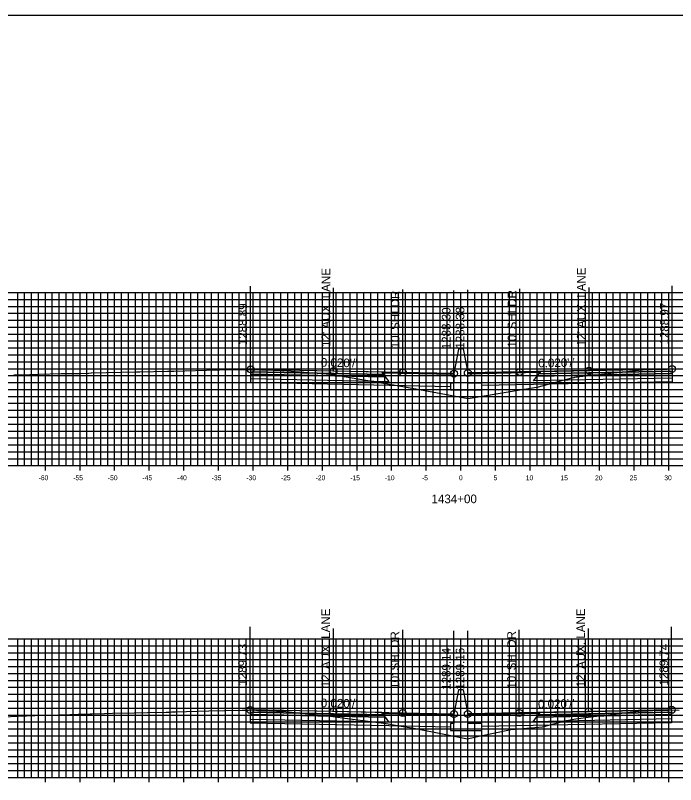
# Model space of a CAD drawing. Extents: x 674939 to 678919, y 750652 to 765176.
# Drawn here: x 678674.2 to 678769.5, y 758391.5 to 758502.6 of the extents above; entities that cross this region are included whole.
import ezdxf

# ---------------------------------------------------------------- set-up
doc = ezdxf.new("R2010")
doc.units = 0
for name, color, linetype in [('Level 10', 7, 'Continuous'), ('Level 17', 7, 'Continuous'), ('Level 18', 7, 'Continuous'), ('Level 19', 7, 'Continuous'), ('Level 20', 7, 'Continuous'), ('Level 22', 7, 'Continuous'), ('Level 23', 7, 'Continuous'), ('Level 4', 7, 'Continuous'), ('Level 8', 7, 'Continuous'), ('Level 9', 7, 'Continuous')]:
    doc.layers.add(name, color=color, linetype=linetype)

msp = doc.modelspace()

# ---------------------------------------------------------------- linework, layer by layer
at = {"layer": 'Level 10'}
for points in [[(678673.98, 758450.67), (678676.27, 758450.71), (678676.43, 758450.71), (678677.58, 758450.76), (678680.82, 758450.84), (678681.07, 758450.84), (678683.36, 758450.86), (678683.42, 758450.86), (678684.76, 758450.9), (678684.77, 758450.91), (678684.78, 758450.91), (678685.16, 758450.93), (678685.18, 758450.93), (678691.68, 758451.09), (678691.98, 758451.1), (678692.17, 758451.1), (678696.18, 758451.17), (678696.94, 758451.2), (678697.1, 758451.2), (678703.4, 758451.37), (678703.66, 758451.38), (678707.67, 758451.44), (678707.78, 758451.44), (678707.79, 758451.44), (678708.15, 758451.44), (678708.15, 758451.44), (678708.37, 758451.44), (678708.4, 758451.43), (678709.74, 758451.37), (678709.78, 758451.37), (678709.81, 758451.37), (678711.53, 758451.33), (678711.55, 758451.33), (678711.62, 758451.33), (678712.77, 758451.28), (678712.78, 758451.29), (678712.78, 758451.29), (678715.86, 758451.07), (678719.7, 758450.76), (678726.77, 758449.57), (678728.53, 758449.26), (678732.54, 758448.55), (678739.6, 758447.23), (678745.95, 758448.32), (678749.71, 758448.94), (678754.56, 758450.22), (678754.79, 758450.29), (678754.86, 758450.3), (678754.98, 758450.34), (678755.22, 758450.36), (678755.34, 758450.38), (678755.71, 758450.42), (678764.65, 758451.38), (678764.66, 758451.37), (678764.7, 758451.36), (678764.76, 758451.36), (678765.97, 758451.42), (678766.21, 758451.43), (678767.77, 758451.47), (678767.99, 758451.48), (678768.33, 758451.47), (678768.96, 758451.51), (678769.03, 758451.52), (678769.05, 758451.52), (678769.28, 758451.53), (678770.34, 758451.52)], [(678671.84, 758401.22), (678674.26, 758401.4), (678674.61, 758401.41), (678677.03, 758401.49), (678678.68, 758401.54), (678682.1, 758401.63), (678682.97, 758401.65), (678683.25, 758401.66), (678684.25, 758401.66), (678684.53, 758401.68), (678684.98, 758401.72), (678685.1, 758401.73), (678685.22, 758401.74), (678687.08, 758401.78), (678688.23, 758401.81), (678691.36, 758401.89), (678693.26, 758401.93), (678695.97, 758401.97), (678696.08, 758401.97), (678696.51, 758401.97), (678696.74, 758401.99), (678697.31, 758402.03), (678702.15, 758402.15), (678704.4, 758402.21), (678706.96, 758402.25), (678707.87, 758402.26), (678708.12, 758402.28), (678708.15, 758402.28), (678708.22, 758402.28), (678708.94, 758402.23), (678709.22, 758402.21), (678709.4, 758402.2), (678709.45, 758402.21), (678709.63, 758402.2), (678711.91, 758402.13), (678712.42, 758402.11), (678712.71, 758402.11), (678712.78, 758402.11), (678712.83, 758402.13), (678717.4, 758401.63), (678719.03, 758401.45), (678719.69, 758401.38), (678720.39, 758401.3), (678721.78, 758401.11), (678727.72, 758400.33), (678729.89, 758399.95), (678731.97, 758399.59), (678736.1, 758398.8), (678739.49, 758398.12), (678740.5, 758398.35), (678745.76, 758399.45), (678749.2, 758399.76), (678750.31, 758399.87), (678753.77, 758400.75), (678755.1, 758400.99), (678756.89, 758401.26), (678764.59, 758402.17), (678764.68, 758402.15), (678764.99, 758402.15), (678765.36, 758402.18), (678765.68, 758402.19), (678766.25, 758402.22), (678766.88, 758402.25), (678767.07, 758402.24), (678767.28, 758402.22), (678767.85, 758402.23), (678768.38, 758402.24), (678768.59, 758402.28), (678768.78, 758402.3), (678768.87, 758402.3), (678768.96, 758402.3), (678770.03, 758402.27)]]:
    msp.add_lwpolyline(points, dxfattribs=at)
at = {"layer": 'Level 17'}
for points in [[(678738.2, 758454.35), (678737.53, 758450.85)], [(678738.86, 758454.43), (678738.86, 758454.43), (678738.2, 758454.43), (678738.2, 758454.35)], [(678738.86, 758454.43), (678739.53, 758450.93)], [(678737.53, 758450.85), (678737.53, 758449.48), (678737.03, 758449.48), (678737.03, 758448.48), (678741.53, 758448.48), (678741.53, 758449.48), (678739.53, 758449.48), (678739.53, 758450.93)], [(678738.2, 758405.19), (678737.53, 758401.69)], [(678738.86, 758405.21), (678738.86, 758405.21), (678738.2, 758405.21), (678738.2, 758405.19)], [(678738.86, 758405.21), (678739.53, 758401.71)], [(678737.53, 758401.69), (678737.53, 758400.32), (678737.03, 758400.32), (678737.03, 758399.32), (678741.53, 758399.32), (678741.53, 758400.32), (678739.53, 758400.32), (678739.53, 758401.71)]]:
    msp.add_lwpolyline(points, dxfattribs=at)
at = {"layer": 'Level 18'}
for points in [[(678737.53, 758450.85), (678730.15, 758451), (678720.15, 758451.2), (678708.15, 758451.44)], [(678769.03, 758451.52), (678757.03, 758451.28), (678747.03, 758451.08), (678739.53, 758450.93)], [(678737.53, 758401.69), (678730.12, 758401.84), (678720.12, 758402.04), (678708.12, 758402.28)], [(678768.96, 758402.3), (678756.96, 758402.06), (678746.96, 758401.86), (678739.53, 758401.71)]]:
    msp.add_lwpolyline(points, dxfattribs=at)
for points in [[(678708.15, 758451.44), (678708.15, 758451.11), (678727.4, 758450.72), (678727.15, 758451.06)], [(678769.03, 758451.52), (678769.03, 758451.19), (678749.78, 758450.8), (678750.03, 758451.14)], [(678727.15, 758451.06), (678737.53, 758450.85), (678737.54, 758450.69), (678727.27, 758450.9)], [(678749.91, 758450.98), (678739.53, 758450.77), (678739.53, 758450.93), (678750.03, 758451.14)], [(678708.12, 758402.28), (678708.12, 758401.95), (678727.37, 758401.57), (678727.12, 758401.9)], [(678727.12, 758401.9), (678737.53, 758401.69), (678737.54, 758401.53), (678727.24, 758401.74)], [(678749.84, 758401.76), (678739.53, 758401.55), (678739.53, 758401.71), (678749.96, 758401.92)], [(678768.96, 758402.3), (678768.96, 758401.97), (678749.71, 758401.58), (678749.96, 758401.92)]]:
    msp.add_lwpolyline(points, close=True, dxfattribs=at)
at = {"layer": 'Level 19'}
for points in [[(678708.15, 758451.11), (678708.15, 758450.78), (678727.65, 758450.39), (678727.4, 758450.72)], [(678708.15, 758450.78), (678708.15, 758450.12), (678728.15, 758449.72), (678727.65, 758450.39)], [(678769.03, 758450.86), (678769.03, 758450.2), (678749.03, 758449.8), (678749.53, 758450.47)], [(678769.03, 758451.19), (678769.03, 758450.86), (678749.53, 758450.47), (678749.78, 758450.8)], [(678708.12, 758401.95), (678708.12, 758401.62), (678727.62, 758401.23), (678727.37, 758401.57)], [(678708.12, 758401.62), (678708.12, 758400.96), (678728.12, 758400.56), (678727.62, 758401.23)], [(678768.96, 758401.64), (678768.96, 758400.98), (678748.96, 758400.58), (678749.46, 758401.25)], [(678768.96, 758401.97), (678768.96, 758401.64), (678749.46, 758401.25), (678749.71, 758401.58)]]:
    msp.add_lwpolyline(points, close=True, dxfattribs=at)
for points in [[(678708.15, 758450.12), (678708.15, 758449.58), (678728.15, 758449.18), (678737.03, 758449)], [(678769.03, 758450.2), (678769.03, 758449.66), (678749.03, 758449.26), (678741.53, 758449.11)], [(678708.12, 758400.96), (678708.12, 758400.42), (678728.12, 758400.02), (678737.03, 758399.84)], [(678768.96, 758400.98), (678768.96, 758400.44), (678748.96, 758400.04), (678741.53, 758399.89)]]:
    msp.add_lwpolyline(points, dxfattribs=at)
at = {"layer": 'Level 20'}
for p, q in [((678638.53, 758462.55), (678838.53, 758462.55)), ((678674.53, 758437.55), (678674.53, 758462.55)), ((678675.53, 758437.55), (678675.53, 758462.55)), ((678676.53, 758437.55), (678676.53, 758462.55)), ((678677.53, 758437.55), (678677.53, 758462.55)), ((678678.53, 758437.55), (678678.53, 758462.55)), ((678679.53, 758437.55), (678679.53, 758462.55)), ((678680.53, 758437.55), (678680.53, 758462.55)), ((678681.53, 758437.55), (678681.53, 758462.55)), ((678682.53, 758437.55), (678682.53, 758462.55)), ((678683.53, 758437.55), (678683.53, 758462.55)), ((678684.53, 758437.55), (678684.53, 758462.55)), ((678685.53, 758437.55), (678685.53, 758462.55)), ((678686.53, 758437.55), (678686.53, 758462.55)), ((678687.53, 758437.55), (678687.53, 758462.55)), ((678688.53, 758437.55), (678688.53, 758462.55)), ((678689.53, 758437.55), (678689.53, 758462.55)), ((678690.53, 758437.55), (678690.53, 758462.55)), ((678691.53, 758437.55), (678691.53, 758462.55)), ((678692.53, 758437.55), (678692.53, 758462.55)), ((678693.53, 758437.55), (678693.53, 758462.55)), ((678694.53, 758437.55), (678694.53, 758462.55)), ((678695.53, 758437.55), (678695.53, 758462.55)), ((678696.53, 758437.55), (678696.53, 758462.55)), ((678697.53, 758437.55), (678697.53, 758462.55)), ((678698.53, 758437.55), (678698.53, 758462.55)), ((678699.53, 758437.55), (678699.53, 758462.55)), ((678700.53, 758437.55), (678700.53, 758462.55)), ((678701.53, 758437.55), (678701.53, 758462.55)), ((678702.53, 758437.55), (678702.53, 758462.55)), ((678703.53, 758437.55), (678703.53, 758462.55)), ((678704.53, 758437.55), (678704.53, 758462.55)), ((678705.53, 758437.55), (678705.53, 758462.55)), ((678706.53, 758437.55), (678706.53, 758462.55)), ((678707.53, 758437.55), (678707.53, 758462.55)), ((678708.53, 758437.55), (678708.53, 758462.55)), ((678709.53, 758437.55), (678709.53, 758462.55)), ((678710.53, 758437.55), (678710.53, 758462.55)), ((678711.53, 758437.55), (678711.53, 758462.55)), ((678712.53, 758437.55), (678712.53, 758462.55)), ((678713.53, 758437.55), (678713.53, 758462.55)), ((678714.53, 758437.55), (678714.53, 758462.55)), ((678715.53, 758437.55), (678715.53, 758462.55)), ((678716.53, 758437.55), (678716.53, 758462.55)), ((678717.53, 758437.55), (678717.53, 758462.55)), ((678718.53, 758437.55), (678718.53, 758462.55)), ((678719.53, 758437.55), (678719.53, 758462.55)), ((678720.53, 758437.55), (678720.53, 758462.55)), ((678721.53, 758437.55), (678721.53, 758462.55)), ((678722.53, 758437.55), (678722.53, 758462.55)), ((678723.53, 758437.55), (678723.53, 758462.55)), ((678724.53, 758437.55), (678724.53, 758462.55)), ((678725.53, 758437.55), (678725.53, 758462.55)), ((678726.53, 758437.55), (678726.53, 758462.55)), ((678727.53, 758437.55), (678727.53, 758462.55)), ((678728.53, 758437.55), (678728.53, 758462.55)), ((678729.53, 758437.55), (678729.53, 758462.55)), ((678730.53, 758437.55), (678730.53, 758462.55)), ((678731.53, 758437.55), (678731.53, 758462.55)), ((678732.53, 758437.55), (678732.53, 758462.55)), ((678733.53, 758437.55), (678733.53, 758462.55)), ((678734.53, 758437.55), (678734.53, 758462.55)), ((678735.53, 758437.55), (678735.53, 758462.55)), ((678736.53, 758437.55), (678736.53, 758462.55)), ((678737.53, 758437.55), (678737.53, 758462.55)), ((678738.53, 758437.55), (678738.53, 758462.55)), ((678739.53, 758437.55), (678739.53, 758462.55)), ((678740.53, 758437.55), (678740.53, 758462.55)), ((678741.53, 758437.55), (678741.53, 758462.55)), ((678742.53, 758437.55), (678742.53, 758462.55)), ((678743.53, 758437.55), (678743.53, 758462.55)), ((678744.53, 758437.55), (678744.53, 758462.55)), ((678745.53, 758437.55), (678745.53, 758462.55)), ((678746.53, 758437.55), (678746.53, 758462.55)), ((678747.53, 758437.55), (678747.53, 758462.55)), ((678748.53, 758437.55), (678748.53, 758462.55)), ((678749.53, 758437.55), (678749.53, 758462.55)), ((678750.53, 758437.55), (678750.53, 758462.55)), ((678751.53, 758437.55), (678751.53, 758462.55)), ((678752.53, 758437.55), (678752.53, 758462.55)), ((678753.53, 758437.55), (678753.53, 758462.55)), ((678754.53, 758437.55), (678754.53, 758462.55)), ((678755.53, 758437.55), (678755.53, 758462.55)), ((678756.53, 758437.55), (678756.53, 758462.55)), ((678757.53, 758437.55), (678757.53, 758462.55)), ((678758.53, 758437.55), (678758.53, 758462.55)), ((678759.53, 758437.55), (678759.53, 758462.55)), ((678760.53, 758437.55), (678760.53, 758462.55)), ((678761.53, 758437.55), (678761.53, 758462.55)), ((678762.53, 758437.55), (678762.53, 758462.55)), ((678763.53, 758437.55), (678763.53, 758462.55)), ((678764.53, 758437.55), (678764.53, 758462.55)), ((678765.53, 758437.55), (678765.53, 758462.55)), ((678766.53, 758437.55), (678766.53, 758462.55)), ((678767.53, 758437.55), (678767.53, 758462.55)), ((678768.53, 758437.55), (678768.53, 758462.55)), ((678638.53, 758461.55), (678838.53, 758461.55)), ((678638.53, 758460.55), (678838.53, 758460.55)), ((678638.53, 758459.55), (678838.53, 758459.55)), ((678638.53, 758458.55), (678838.53, 758458.55)), ((678638.53, 758457.55), (678838.53, 758457.55)), ((678638.53, 758456.55), (678838.53, 758456.55)), ((678638.53, 758455.55), (678838.53, 758455.55)), ((678638.53, 758454.55), (678838.53, 758454.55)), ((678638.53, 758453.55), (678838.53, 758453.55)), ((678638.53, 758452.55), (678838.53, 758452.55)), ((678638.53, 758451.55), (678838.53, 758451.55)), ((678638.53, 758450.55), (678838.53, 758450.55)), ((678638.53, 758449.55), (678838.53, 758449.55)), ((678638.53, 758448.55), (678838.53, 758448.55)), ((678638.53, 758447.55), (678838.53, 758447.55)), ((678638.53, 758446.55), (678838.53, 758446.55)), ((678638.53, 758445.55), (678838.53, 758445.55)), ((678638.53, 758444.55), (678838.53, 758444.55)), ((678638.53, 758443.55), (678838.53, 758443.55)), ((678638.53, 758442.55), (678838.53, 758442.55)), ((678638.53, 758441.55), (678838.53, 758441.55)), ((678638.53, 758440.55), (678838.53, 758440.55)), ((678638.53, 758439.55), (678838.53, 758439.55)), ((678638.53, 758438.55), (678838.53, 758438.55)), ((678638.53, 758437.55), (678838.53, 758437.55)), ((678638.53, 758412.55), (678838.53, 758412.55)), ((678638.53, 758411.55), (678838.53, 758411.55)), ((678674.53, 758392.55), (678674.53, 758412.55)), ((678675.53, 758392.55), (678675.53, 758412.55)), ((678676.53, 758392.55), (678676.53, 758412.55)), ((678677.53, 758392.55), (678677.53, 758412.55)), ((678678.53, 758392.55), (678678.53, 758412.55)), ((678679.53, 758392.55), (678679.53, 758412.55)), ((678680.53, 758392.55), (678680.53, 758412.55)), ((678681.53, 758392.55), (678681.53, 758412.55)), ((678682.53, 758392.55), (678682.53, 758412.55)), ((678683.53, 758392.55), (678683.53, 758412.55)), ((678684.53, 758392.55), (678684.53, 758412.55)), ((678685.53, 758392.55), (678685.53, 758412.55)), ((678686.53, 758392.55), (678686.53, 758412.55)), ((678687.53, 758392.55), (678687.53, 758412.55)), ((678688.53, 758392.55), (678688.53, 758412.55)), ((678689.53, 758392.55), (678689.53, 758412.55)), ((678690.53, 758392.55), (678690.53, 758412.55)), ((678691.53, 758392.55), (678691.53, 758412.55)), ((678692.53, 758392.55), (678692.53, 758412.55)), ((678693.53, 758392.55), (678693.53, 758412.55)), ((678694.53, 758392.55), (678694.53, 758412.55)), ((678695.53, 758392.55), (678695.53, 758412.55)), ((678696.53, 758392.55), (678696.53, 758412.55)), ((678697.53, 758392.55), (678697.53, 758412.55)), ((678698.53, 758392.55), (678698.53, 758412.55)), ((678699.53, 758392.55), (678699.53, 758412.55)), ((678700.53, 758392.55), (678700.53, 758412.55)), ((678701.53, 758392.55), (678701.53, 758412.55)), ((678702.53, 758392.55), (678702.53, 758412.55)), ((678703.53, 758392.55), (678703.53, 758412.55)), ((678704.53, 758392.55), (678704.53, 758412.55)), ((678705.53, 758392.55), (678705.53, 758412.55)), ((678706.53, 758392.55), (678706.53, 758412.55)), ((678707.53, 758392.55), (678707.53, 758412.55)), ((678708.53, 758392.55), (678708.53, 758412.55)), ((678709.53, 758392.55), (678709.53, 758412.55)), ((678710.53, 758392.55), (678710.53, 758412.55)), ((678711.53, 758392.55), (678711.53, 758412.55)), ((678712.53, 758392.55), (678712.53, 758412.55)), ((678713.53, 758392.55), (678713.53, 758412.55)), ((678714.53, 758392.55), (678714.53, 758412.55)), ((678715.53, 758392.55), (678715.53, 758412.55)), ((678716.53, 758392.55), (678716.53, 758412.55)), ((678717.53, 758392.55), (678717.53, 758412.55)), ((678718.53, 758392.55), (678718.53, 758412.55)), ((678719.53, 758392.55), (678719.53, 758412.55)), ((678720.53, 758392.55), (678720.53, 758412.55)), ((678721.53, 758392.55), (678721.53, 758412.55)), ((678722.53, 758392.55), (678722.53, 758412.55)), ((678723.53, 758392.55), (678723.53, 758412.55)), ((678724.53, 758392.55), (678724.53, 758412.55)), ((678725.53, 758392.55), (678725.53, 758412.55)), ((678726.53, 758392.55), (678726.53, 758412.55)), ((678727.53, 758392.55), (678727.53, 758412.55)), ((678728.53, 758392.55), (678728.53, 758412.55)), ((678729.53, 758392.55), (678729.53, 758412.55)), ((678730.53, 758392.55), (678730.53, 758412.55)), ((678731.53, 758392.55), (678731.53, 758412.55)), ((678732.53, 758392.55), (678732.53, 758412.55)), ((678733.53, 758392.55), (678733.53, 758412.55)), ((678734.53, 758392.55), (678734.53, 758412.55)), ((678735.53, 758392.55), (678735.53, 758412.55)), ((678736.53, 758392.55), (678736.53, 758412.55)), ((678737.53, 758392.55), (678737.53, 758412.55)), ((678738.53, 758392.55), (678738.53, 758412.55)), ((678739.53, 758392.55), (678739.53, 758412.55)), ((678740.53, 758392.55), (678740.53, 758412.55)), ((678741.53, 758392.55), (678741.53, 758412.55)), ((678742.53, 758392.55), (678742.53, 758412.55)), ((678743.53, 758392.55), (678743.53, 758412.55)), ((678744.53, 758392.55), (678744.53, 758412.55)), ((678745.53, 758392.55), (678745.53, 758412.55)), ((678746.53, 758392.55), (678746.53, 758412.55)), ((678747.53, 758392.55), (678747.53, 758412.55)), ((678748.53, 758392.55), (678748.53, 758412.55)), ((678749.53, 758392.55), (678749.53, 758412.55)), ((678750.53, 758392.55), (678750.53, 758412.55)), ((678751.53, 758392.55), (678751.53, 758412.55)), ((678752.53, 758392.55), (678752.53, 758412.55)), ((678753.53, 758392.55), (678753.53, 758412.55)), ((678754.53, 758392.55), (678754.53, 758412.55)), ((678755.53, 758392.55), (678755.53, 758412.55)), ((678756.53, 758392.55), (678756.53, 758412.55)), ((678757.53, 758392.55), (678757.53, 758412.55)), ((678758.53, 758392.55), (678758.53, 758412.55)), ((678759.53, 758392.55), (678759.53, 758412.55)), ((678760.53, 758392.55), (678760.53, 758412.55)), ((678761.53, 758392.55), (678761.53, 758412.55)), ((678762.53, 758392.55), (678762.53, 758412.55)), ((678763.53, 758392.55), (678763.53, 758412.55)), ((678764.53, 758392.55), (678764.53, 758412.55)), ((678765.53, 758392.55), (678765.53, 758412.55)), ((678766.53, 758392.55), (678766.53, 758412.55)), ((678767.53, 758392.55), (678767.53, 758412.55)), ((678768.53, 758392.55), (678768.53, 758412.55)), ((678638.53, 758410.55), (678838.53, 758410.55)), ((678638.53, 758409.55), (678838.53, 758409.55)), ((678638.53, 758408.55), (678838.53, 758408.55)), ((678638.53, 758407.55), (678838.53, 758407.55)), ((678638.53, 758406.55), (678838.53, 758406.55)), ((678638.53, 758405.55), (678838.53, 758405.55)), ((678638.53, 758404.55), (678838.53, 758404.55)), ((678638.53, 758403.55), (678838.53, 758403.55)), ((678638.53, 758402.55), (678838.53, 758402.55)), ((678638.53, 758401.55), (678838.53, 758401.55)), ((678638.53, 758400.55), (678838.53, 758400.55)), ((678638.53, 758399.55), (678838.53, 758399.55)), ((678638.53, 758398.55), (678838.53, 758398.55)), ((678638.53, 758397.55), (678838.53, 758397.55)), ((678638.53, 758396.55), (678838.53, 758396.55)), ((678638.53, 758395.55), (678838.53, 758395.55)), ((678638.53, 758394.55), (678838.53, 758394.55)), ((678638.53, 758393.55), (678838.53, 758393.55)), ((678638.53, 758392.55), (678838.53, 758392.55))]:
    msp.add_line(p, q, dxfattribs=at)
at = {"layer": 'Level 23'}
for p, q in [((678708.15, 758451.44), (678708.15, 758463.44)), ((678720.15, 758451.2), (678720.15, 758463.2)), ((678730.15, 758451), (678730.15, 758463)), ((678737.53, 758450.85), (678737.53, 758462.85)), ((678739.53, 758450.93), (678739.53, 758462.93)), ((678747.03, 758451.08), (678747.03, 758463.08)), ((678757.03, 758451.28), (678757.03, 758463.28)), ((678769.03, 758451.52), (678769.03, 758463.52)), ((678708.12, 758402.28), (678708.12, 758414.28)), ((678720.12, 758402.04), (678720.12, 758414.04)), ((678730.12, 758401.84), (678730.12, 758413.84)), ((678737.53, 758401.69), (678737.53, 758413.69)), ((678739.53, 758401.71), (678739.53, 758413.71)), ((678746.96, 758401.86), (678746.96, 758413.86)), ((678756.96, 758402.06), (678756.96, 758414.06)), ((678768.96, 758402.3), (678768.96, 758414.3))]:
    msp.add_line(p, q, dxfattribs=at)
at = {"layer": 'Level 4'}
msp.add_lwpolyline([(678578.53, 758282.55), (678918.53, 758282.55), (678918.53, 758502.55), (678578.53, 758502.55)], close=True, dxfattribs=at)
for centre in [(678708.15, 758451.44), (678720.15, 758451.2), (678730.15, 758451), (678739.53, 758450.93), (678747.03, 758451.08), (678757.03, 758451.28), (678769.03, 758451.52), (678737.53, 758450.85), (678708.12, 758402.28), (678768.96, 758402.3), (678720.12, 758402.04), (678730.12, 758401.84), (678737.53, 758401.69), (678739.53, 758401.71), (678746.96, 758401.86), (678756.96, 758402.06)]:
    msp.add_circle(centre, 0.5, dxfattribs=at)
at = {"layer": 'Level 8'}
for p, q in [((678678.53, 758436.85), (678678.53, 758438.25)), ((678683.53, 758436.85), (678683.53, 758438.25)), ((678688.53, 758436.85), (678688.53, 758438.25)), ((678693.53, 758436.85), (678693.53, 758438.25)), ((678698.53, 758436.85), (678698.53, 758438.25)), ((678703.53, 758436.85), (678703.53, 758438.25)), ((678708.53, 758436.85), (678708.53, 758438.25)), ((678713.53, 758436.85), (678713.53, 758438.25)), ((678718.53, 758436.85), (678718.53, 758438.25)), ((678723.53, 758436.85), (678723.53, 758438.25)), ((678728.53, 758436.85), (678728.53, 758438.25)), ((678733.53, 758436.85), (678733.53, 758438.25)), ((678738.53, 758436.85), (678738.53, 758438.25)), ((678743.53, 758436.85), (678743.53, 758438.25)), ((678748.53, 758436.85), (678748.53, 758438.25)), ((678753.53, 758436.85), (678753.53, 758438.25)), ((678758.53, 758436.85), (678758.53, 758438.25)), ((678763.53, 758436.85), (678763.53, 758438.25)), ((678768.53, 758436.85), (678768.53, 758438.25)), ((678638.53, 758437.55), (678838.53, 758437.55)), ((678678.53, 758391.85), (678678.53, 758393.25)), ((678683.53, 758391.85), (678683.53, 758393.25)), ((678688.53, 758391.85), (678688.53, 758393.25)), ((678693.53, 758391.85), (678693.53, 758393.25)), ((678698.53, 758391.85), (678698.53, 758393.25)), ((678703.53, 758391.85), (678703.53, 758393.25)), ((678708.53, 758391.85), (678708.53, 758393.25)), ((678713.53, 758391.85), (678713.53, 758393.25)), ((678718.53, 758391.85), (678718.53, 758393.25)), ((678723.53, 758391.85), (678723.53, 758393.25)), ((678728.53, 758391.85), (678728.53, 758393.25)), ((678733.53, 758391.85), (678733.53, 758393.25)), ((678738.53, 758391.85), (678738.53, 758393.25)), ((678743.53, 758391.85), (678743.53, 758393.25)), ((678748.53, 758391.85), (678748.53, 758393.25)), ((678753.53, 758391.85), (678753.53, 758393.25)), ((678758.53, 758391.85), (678758.53, 758393.25)), ((678763.53, 758391.85), (678763.53, 758393.25)), ((678768.53, 758391.85), (678768.53, 758393.25)), ((678638.53, 758392.55), (678838.53, 758392.55))]:
    msp.add_line(p, q, dxfattribs=at)

# ---------------------------------------------------------------- texts
at = {"layer": 'Level 22'}
for rotation, p in [(358.8542, (678718.29, 758451.84)), (1.1458, (678749.71, 758451.73)), (358.8542, (678718.28, 758402.68)), (1.1458, (678749.67, 758402.51))]:
    msp.add_text("0.020'/'", height=1.25, rotation=rotation, dxfattribs=at).set_placement(p)
at = {"layer": 'Level 23'}
for s, p in [("12' AUX. LANE", (678719.65, 758454.7)), ("12' AUX. LANE", (678756.53, 758454.78)), ("10' SHLDR", (678729.65, 758454.5)), ("10' SHLDR", (678746.53, 758454.58)), ('1288.89', (678707.65, 758454.94)), ('1288.30', (678737.03, 758454.35)), ('1288.38', (678739.03, 758454.43)), ('1288.97', (678768.53, 758455.02)), ("12' AUX. LANE", (678719.62, 758405.54)), ("12' AUX. LANE", (678756.46, 758405.56)), ("10' SHLDR", (678729.62, 758405.34)), ("10' SHLDR", (678746.46, 758405.36)), ('1289.73', (678707.62, 758405.78)), ('1289.74', (678768.46, 758405.8)), ('1289.14', (678737.03, 758405.19)), ('1289.16', (678739.03, 758405.21))]:
    msp.add_text(s, height=1.25, rotation=90, dxfattribs=at).set_placement(p)
at = {"layer": 'Level 9'}
for s, height, p in [('-60', 0.7, (678677.55, 758435.45)), ('-55', 0.7, (678682.55, 758435.45)), ('-50', 0.7, (678687.55, 758435.45)), ('-45', 0.7, (678692.55, 758435.45)), ('-40', 0.7, (678697.55, 758435.45)), ('-35', 0.7, (678702.55, 758435.45)), ('-30', 0.7, (678707.55, 758435.45)), ('-25', 0.7, (678712.55, 758435.45)), ('-20', 0.7, (678717.55, 758435.45)), ('-15', 0.7, (678722.55, 758435.45)), ('-10', 0.7, (678727.55, 758435.45)), ('-5', 0.7, (678732.9, 758435.45)), ('0', 0.7, (678738.25, 758435.45)), ('5', 0.7, (678743.25, 758435.45)), ('10', 0.7, (678747.9, 758435.45)), ('15', 0.7, (678752.9, 758435.45)), ('20', 0.7, (678757.9, 758435.45)), ('25', 0.7, (678762.9, 758435.45)), ('30', 0.7, (678767.9, 758435.45)), ('1434+00', 1.25, (678734.28, 758432.13))]:
    msp.add_text(s, height=height, dxfattribs=at).set_placement(p)

doc.saveas('drawing.dxf')
